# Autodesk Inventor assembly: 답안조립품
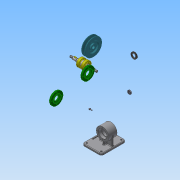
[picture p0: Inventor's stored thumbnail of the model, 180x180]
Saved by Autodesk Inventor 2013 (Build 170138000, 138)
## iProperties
Created: 2019-09
Part Number: 답안조립품
Document SubType Name: Assembly
Designer: Administrator
Author: Administrator
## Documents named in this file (10)
- C:\Users\Administrator\Desktop\490904V1040\답안조립품.iam
- C:\Users\Administrator\Desktop\490904V1040\본체.ipt
- C:\Users\Administrator\Desktop\490904V1040\V-벨트풀리.ipt
- C:\Users\Administrator\Desktop\490904V1040\너트 M10x1.ipt
- C:\Users\Administrator\Desktop\490904V1040\베어링 6004.ipt
- C:\Users\Administrator\Desktop\490904V1040\볼트 M4.ipt
- C:\Users\Administrator\Desktop\490904V1040\오일 실 17 30 5.ipt
- C:\Users\Administrator\Desktop\490904V1040\축.ipt
- C:\Users\Administrator\Desktop\490904V1040\커버.ipt
- C:\Users\Administrator\Desktop\490904V1040\키 5 x 5 x 12.ipt
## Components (1 placed, 1 different names)
1. V-벨트풀리:1
